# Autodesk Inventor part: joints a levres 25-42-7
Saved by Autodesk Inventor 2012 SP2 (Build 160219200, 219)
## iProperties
Created: 2013-04
Part Number: joints a levres 25-42-7
Material: Default
Document SubType Name: Modeling
Designer: papa
Density: 1 g/cm^3
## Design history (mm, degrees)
node "joints a levres 25-42-71"
node "joints a levres 25-42-7"
node "Base1"
